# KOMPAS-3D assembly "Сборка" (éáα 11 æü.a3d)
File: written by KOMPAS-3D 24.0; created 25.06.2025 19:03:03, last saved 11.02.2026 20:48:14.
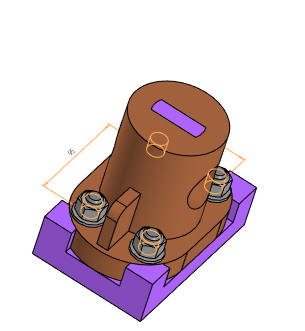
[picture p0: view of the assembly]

Document properties: Автор: Helen; Полное имя файла: C:\Для ноута\Инженерная графика\ППЭ 2025-2026\Варианты 1-38\Вариант 11 СБ\Решение 11\Вар 11 СБ\Вар 11 СБ.a3d

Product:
- Component [detail]: Основание  | designation Вариант 11  | qty 1  | Масса: 3.586869; Автор: Helen; source file: Основание вар 11.m3d
- Component [detail]: Nodes  | qty 1  | Масса: 3.848044; Автор: Helen; source file: Корпус вар 11.m3d
- Component [detail]: Болт М14x60 ГОСТ 15591-70  | qty 7  | Масса: 0.091885; source file: Болт М14x60 ГОСТ 15591-70.m3d
- Component [detail]: Деталь  | qty 1  | Автор: Helen; source file: Деталь.m3d
- Component [detail]: Сборка  | qty 7  | Масса: 0.008612; Автор: PC321; source file: Шайба 14.m3d
- Component [detail]: Сборка  | qty 5  | Масса: 0.02533; Автор: PC321; source file: Гайка М14.m3d
- Part/product: Сборка
    Масса: 8.265039

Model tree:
1. Линейный размер:1  (with: Грань.Операция без истории:1, Ребро.Операция без истории:1)
     Значение = 53.6231
2. Линейный размер:2  (with: Грань.Операция без истории:1, Ребро.Операция без истории:1)
     Значение = 94.9951
3. Массив по сетке:2  (with: Ребро.Элемент выдавливания:1, Элемент выдавливания:6, Операция без истории:1, Элемент выдавливания:1, Грань.Операция без истории:1, Грань.Элемент выдавливания:1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)  (labels: Фаска:3; Фаска наружная:2; Ребро.Элемент выдавливания:3.Экземпляр ( 2 ))  (4 pattern instances)
     Шаг 1 = 95; Угол раствора = 90; Шаг 2 = 53.62; Ориентация = 2

Referenced files in C:\Для ноута\Инженерная графика\ППЭ 2025-2026\Варианты 1-38\Вариант 11 СБ\Решение 11\Вар 11 СБ\: Основание вар 11.m3d, Корпус вар 11.m3d, Болт М14x60 ГОСТ 15591-70.m3d, Шайба 14.m3d, Деталь.m3d, Гайка М14.m3d
Referenced files in D:\MY\WORK\MPEI\ППЭ_2025-2026\Варианты\Вар 11 СБ\: Болт М14x60 ГОСТ 15591-70.m3d, Шайба 14.m3d
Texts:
  Вариант 11 Основание
  Болт М14x60 ГОСТ 15591-70 (1)
  Сборка (1)
  Болт М14x60 ГОСТ 15591-70 (2)
  Сборка (2)
  Болт М14x60 ГОСТ 15591-70 (3)
  Сборка (3)
  Болт М14x60 ГОСТ 15591-70 (4)
  Сборка (4)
